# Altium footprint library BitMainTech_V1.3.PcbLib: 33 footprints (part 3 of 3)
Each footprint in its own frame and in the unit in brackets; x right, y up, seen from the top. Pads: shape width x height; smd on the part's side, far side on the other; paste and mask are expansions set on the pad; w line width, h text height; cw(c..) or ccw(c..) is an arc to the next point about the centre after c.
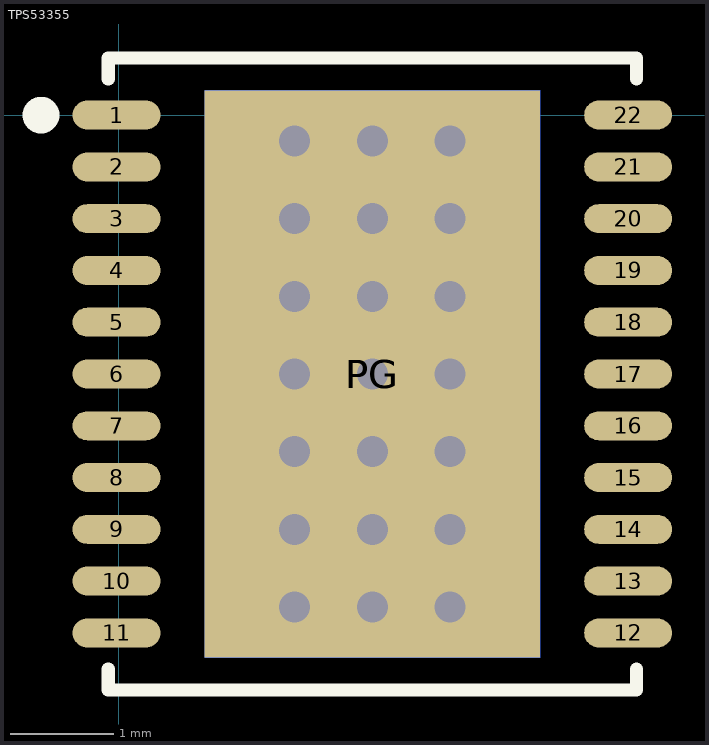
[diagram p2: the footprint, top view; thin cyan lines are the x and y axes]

## TPS53355 [mm]
height 1.5
pads (24):
  oval 0.85x0.28 smd: 1(-0.02,0) 2(-0.02,-0.5) 3(-0.02,-1) 4(-0.02,-1.5) 5(-0.02,-2) 6(-0.02,-2.5) 7(-0.02,-3) 8(-0.02,-3.5) 9(-0.02,-4) 10(-0.02,-4.5) 11(-0.02,-5) 12(4.92,-5) 13(4.92,-4.5) 14(4.92,-4) 15(4.92,-3.5) 16(4.92,-3) 17(4.92,-2.5) 18(4.92,-2) 19(4.92,-1.5) 20(4.92,-1) 21(4.92,-0.5) 22(4.92,0)
  rect 3.24x5.48 smd: PG(2.45,-2.5)
  rect 3.24x5.48 smd far side: PG(2.45,-2.5)
via 2.45,-2.5 diameter 0.5 hole 0.3
via 2.45,-1.75 diameter 0.5 hole 0.3
via 2.45,-1 diameter 0.5 hole 0.3
via 2.45,-0.25 diameter 0.5 hole 0.3
via 2.45,-3.25 diameter 0.5 hole 0.3
via 2.45,-4 diameter 0.5 hole 0.3
via 2.45,-4.75 diameter 0.5 hole 0.3
via 3.2,-2.5 diameter 0.5 hole 0.3
via 3.2,-1.75 diameter 0.5 hole 0.3
via 3.2,-3.25 diameter 0.5 hole 0.3
via 3.2,-4 diameter 0.5 hole 0.3
via 3.2,-4.75 diameter 0.5 hole 0.3
via 3.2,-1 diameter 0.5 hole 0.3
via 3.2,-0.25 diameter 0.5 hole 0.3
via 1.7,-0.25 diameter 0.5 hole 0.3
via 1.7,-1 diameter 0.5 hole 0.3
via 1.7,-1.75 diameter 0.5 hole 0.3
via 1.7,-2.5 diameter 0.5 hole 0.3
via 1.7,-3.25 diameter 0.5 hole 0.3
via 1.7,-4 diameter 0.5 hole 0.3
via 1.7,-4.75 diameter 0.5 hole 0.3
Top Overlay:
  circle w0.254: c-0.75,0 r0.05
  lines w0.127: -0.1,-5.35 -0.1,-5.55 5,-5.55 5,-5.35 ; -0.1,0.35 -0.1,0.55 5,0.55 5,0.35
